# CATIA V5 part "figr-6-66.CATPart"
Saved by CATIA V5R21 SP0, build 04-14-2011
Part number: Part2
Bounding box of the stored display mesh (mm): x -48.023 to 47.984, y -42.839 to 53.196, z 0 to 122.21
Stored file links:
  D:\CATIA V5R21 E-RESOURCES\CATIA-V5R21\catia-v5r21-prt\c06-catia-v5r21-prt\c06-catia-v5r21-figr-6-66.CATPart
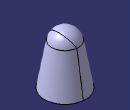
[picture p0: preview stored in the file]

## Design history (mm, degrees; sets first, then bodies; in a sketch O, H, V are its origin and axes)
Body1 (main body)
  Sketch1 on yz-plane, origin (0, 0, 0), H (0, 1, 0), V (0, 0, 1)
    axis line L1 (-55.8323, 90.9269) -> (61.0167, 90.9269)
    arc A1 centre (5.1844, 90.9269) radius 31.5054 from (36.6898, 90.9269) to (-26.3209, 90.9269) ccw
    point P3 (5.1844, 90.9269)
    point P4 (36.6898, 90.9269)
    point P5 (-26.3209, 90.9269)
    line L2 (-26.3209, 90.9269) -> (36.6898, 90.9269)
    horizontal: L1 H, L2 H
    coincidence: P3 L1, P4 L1, P5 L1
  Shaft1: profile Sketch1, axis Sketch1.L1, angle 360
  Draft1: Angle 10, Parting xy-plane, PullDir (0, 0, 1), SupportToDraft face of Shaft1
